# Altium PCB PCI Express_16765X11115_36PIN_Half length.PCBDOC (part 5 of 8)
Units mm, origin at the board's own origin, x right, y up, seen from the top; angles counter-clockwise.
Board outline 178 x 110.97 mm, 10 copper layers (Top Layer, Int1 (GND), Int2 (Sign), Int3 (Sign), Int4 (PWR), Int5 (GND), Int6 (Sign), Int7 (Sign), Int8 (GND), Bottom Layer), stack 1.429 mm thick; 528 components, 525 nets, 2272 pads, 1491 vias.
Unrouted connection lines stored in the file: 373.
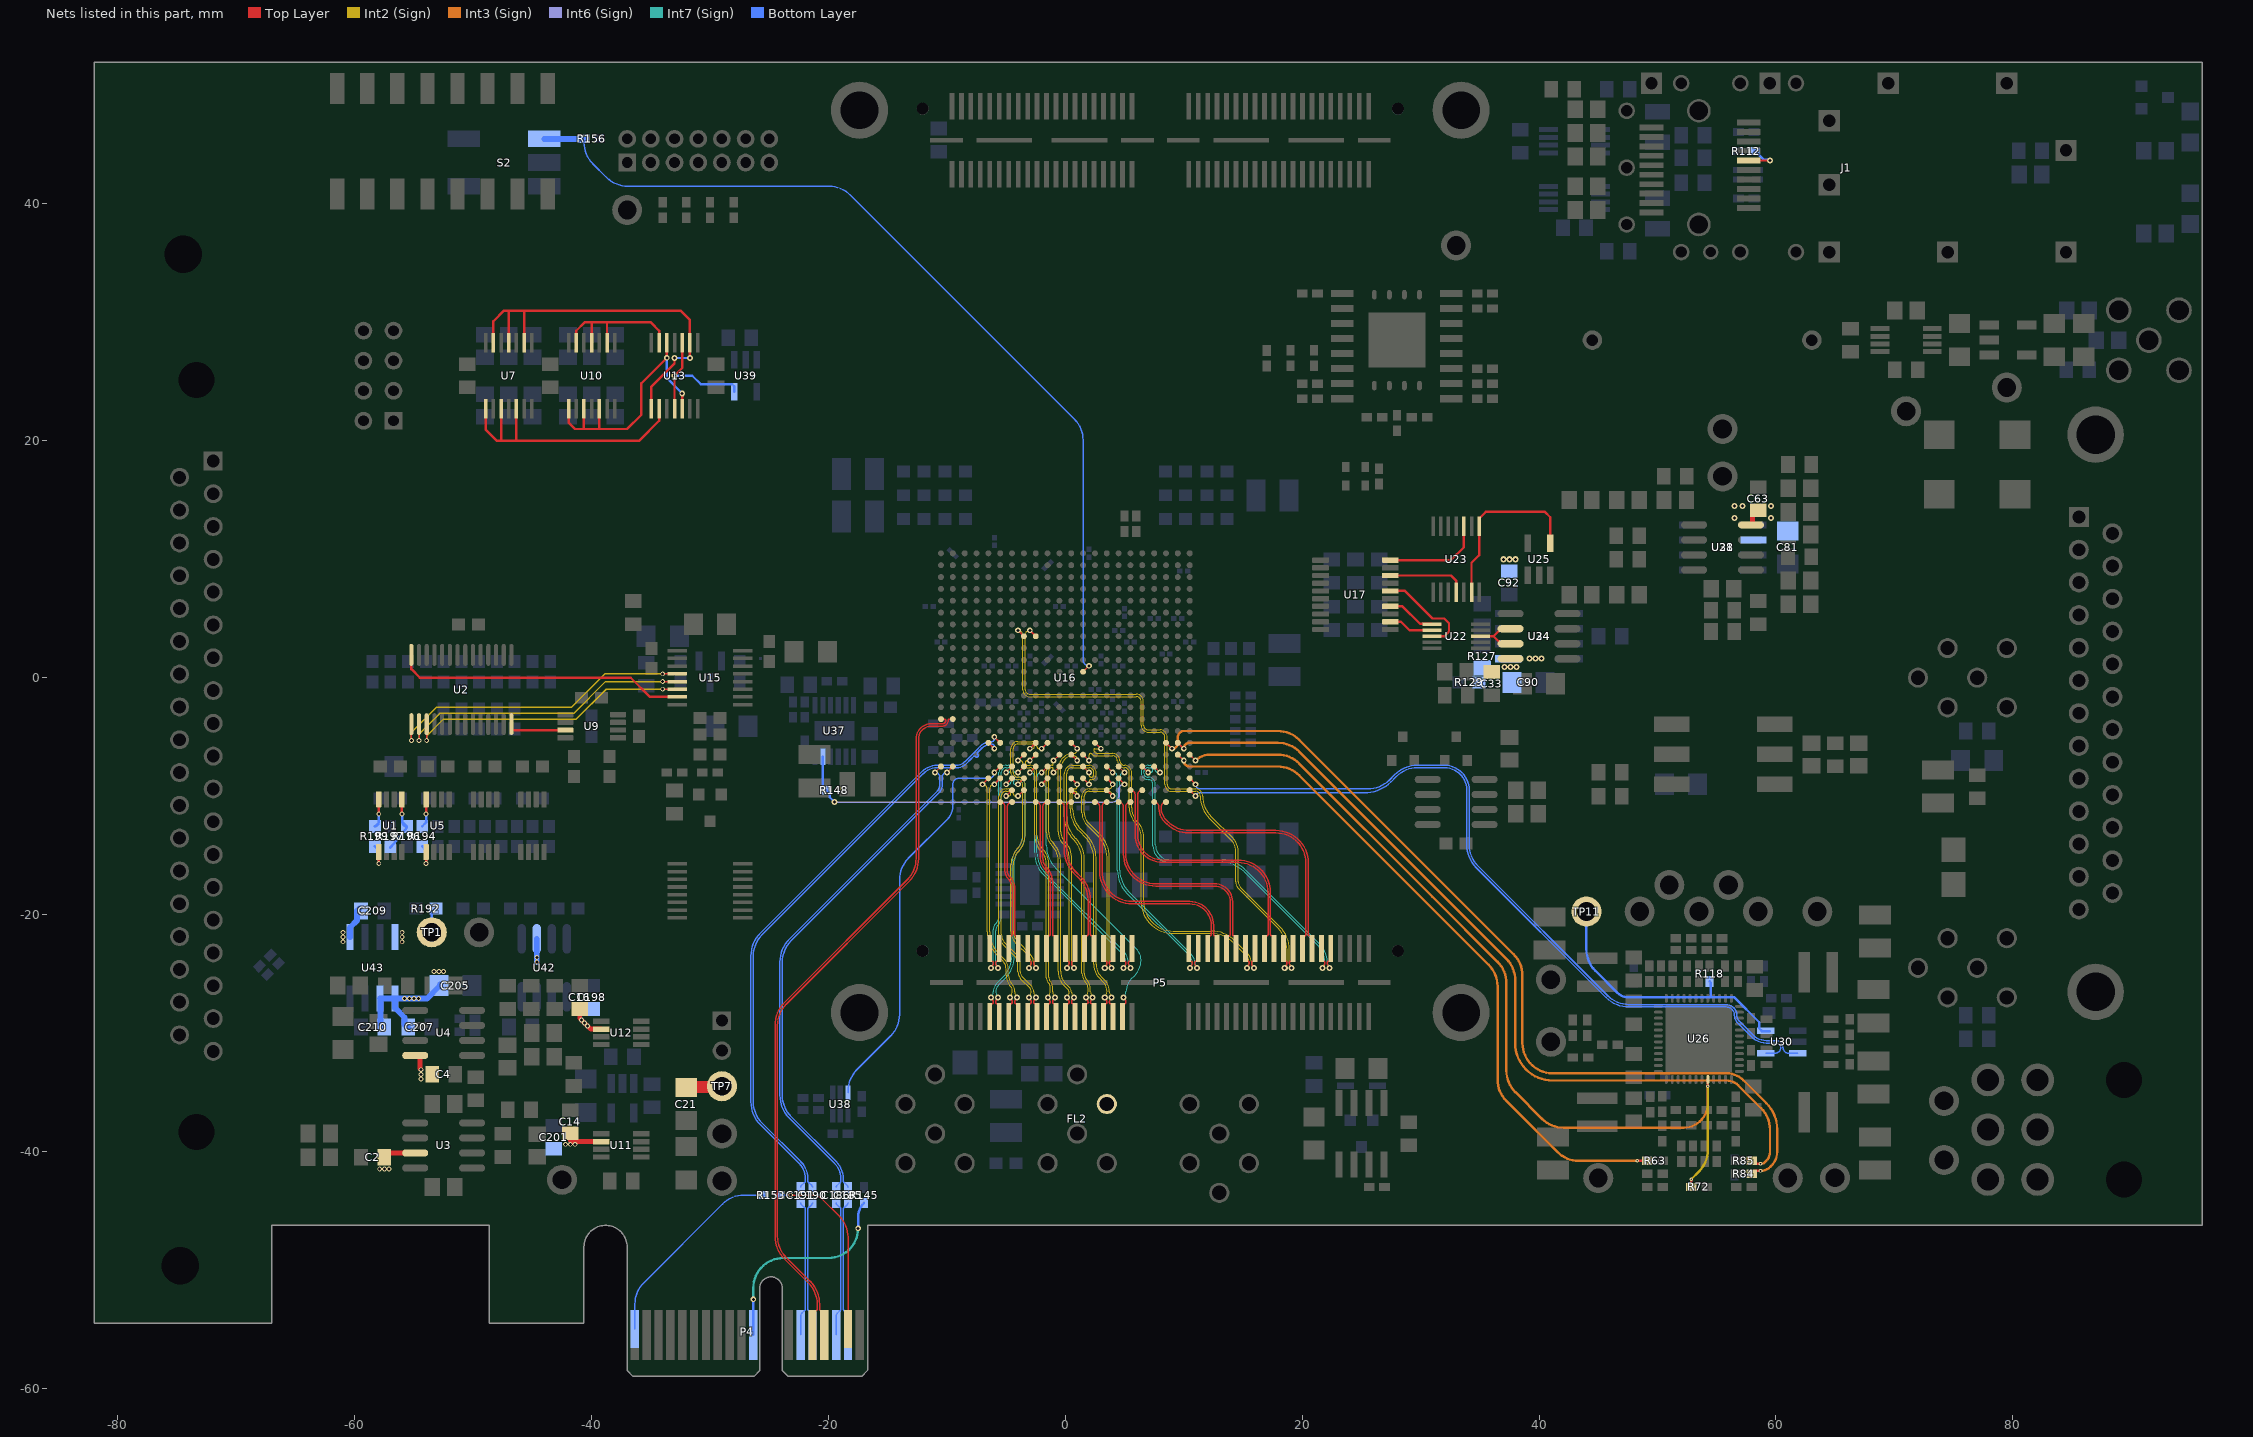
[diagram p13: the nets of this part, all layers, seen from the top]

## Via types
v1: diameter 0.483, hole 0.254, Top Layer to Bottom Layer, tented both sides, 740 vias
v2: diameter 0.508, hole 0.254, Top Layer to Bottom Layer, tented both sides, 302 vias
v3: diameter 0.406, hole 0.254, Top Layer to Bottom Layer, tented both sides, 267 vias
v4: diameter 0.305, hole 0.152, Top Layer to Bottom Layer, tented both sides, 95 vias
v5: diameter 0.5, hole 0.254, Top Layer to Bottom Layer, tented both sides, 50 vias
v6: diameter 0.45, hole 0.254, Top Layer to Bottom Layer, tented both sides, 23 vias
v7: diameter 0.6, hole 0.254, Top Layer to Bottom Layer, tented both sides, 14 vias

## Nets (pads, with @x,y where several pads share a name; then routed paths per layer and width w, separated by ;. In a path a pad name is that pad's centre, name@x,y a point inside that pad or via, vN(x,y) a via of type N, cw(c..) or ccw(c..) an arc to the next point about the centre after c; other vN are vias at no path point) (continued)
NetR194_1: R194.1 U5.8 | length 2.4
  Top Layer w0.203: v3(-53.975,-11.5) U5.8@-53.975,-10.275
  Bottom Layer w0.203: R194.1@-54.3,-12.55 R194.1@-53.975,-12.225 ; R194.1@-54,-12.2 R194.1@-53.975,-12.225 ; v3(-53.975,-11.5) R194.1@-53.975,-12.225
NetR194_2: R194.2 U5.1 | length 2.7
  Top Layer w0.203: v3@-53.975,-15.8 U5.1@-53.975,-14.725
  Bottom Layer w0.203: R194.2@-54.3,-14.25 -53.975,-14.575 v3(-53.975,-15.7)
NetR196_1: R196.1 R197.2 U1.5 | length 5.3
  Top Layer w0.203: v3(-56.025,-11.5) U1.5@-56.025,-10.275 cw(c-56.025,-10.3) U1.5@-56,-10.3
  Bottom Layer w0.203: R197.2@-57,-14.35 -56.951,-14.29 R196.1@-55.6,-12.65 ; v3(-56.025,-11.5) -55.998,-11.527 -55.998,-12.152 R196.1@-55.6,-12.55 cw(c-55.6,-12.15) R196.1@-56,-12.15
NetR199_1: R199.1 U1.8 | length 2.9
  Top Layer w0.203: U1.8@-58,-10.3 cw(c-57.975,-10.3) U1.8@-57.975,-10.275 v3(-57.975,-11.5)
  Bottom Layer w0.203: R199.1@-58,-12.25 cw(c-58.3,-12.25) R199.1@-58.3,-12.55 -57.975,-12.225 v3(-57.975,-11.5)
NetR199_2: R199.2 U1.1 | length 2.6
  Top Layer w0.203: v3(-57.975,-15.7) U1.1@-57.975,-14.725
  Bottom Layer w0.203: R199.2@-58.3,-14.25 -57.975,-14.575 -58,-14.6 -57.975,-14.625 v3(-57.975,-15.7)
NetU2_14: U2.14 U15.7 | length 24.6
  Top Layer w0.203: U2.14@-55.225,1.925 -55.225,0.725 -54.5,0 -36.7,0 -35.075,-1.625 U15.7@-32.775,-1.625
NetU2_15: U2.15 U15.4 | length 26.6
  Top Layer w0.127: v3(-55.225,-5.3) U2.15@-55.225,-3.925 ; v3(-34,0.325) U15.4@-32.775,0.325
  Int2 (Sign) w0.127: v3(-55.225,-5.3) -55.225,-4.625 -53.1,-2.5 -41.699,-2.5 -38.874,0.325 v3(-34,0.325)
NetU2_16: U2.16 U15.5 | length 25.5
  Top Layer w0.127: v3(-54.575,-5.3) U2.16@-54.575,-3.925 ; v3(-34,-0.325) U15.5@-32.775,-0.325
  Int2 (Sign) w0.127: v3(-54.575,-5.3) -54.575,-4.775 -52.8,-3 -41.499,-3 -38.824,-0.325 v3(-34,-0.325)
NetU2_17: U2.17 U15.6 | length 24.5
  Top Layer w0.127: v3(-53.925,-5.3) U2.17@-53.925,-3.925 ; v3(-34,-0.975) U15.6@-32.775,-0.975
  Int2 (Sign) w0.127: v3(-53.925,-5.3) -53.925,-4.925 -52.5,-3.5 -41.299,-3.5 -38.774,-0.975 v3(-34,-0.975)
NetU2_28: U2.28 U9.3 | length 4.9
  Top Layer w0.203: U2.28@-46.775,-3.925 -46.775,-4.357 -46.707,-4.425 -42.325,-4.425 U9.3@-42.3,-4.4
NetU7_1: U7.1 U7.3 U7.5 U13.9 | length 24
  Top Layer w0.203: U7.1@-48.95,22.725 -48.95,20.95 -48,20 -47.65,20 ; U7.3@-47.65,22.725 -47.65,20 ; U7.5@-46.35,22.725 -46.35,20.05 -46.4,20 ; U13.9@-34.3,22.725 -34.3,21.7 -36,20 -46.4,20 ; -47.65,20 -46.4,20
NetU7_9: U7.9 U7.11 U7.13 U13.2 U13.8 | length 34.2
  Top Layer w0.203: U7.13@-48.3,28.275 -48.3,30.1 -47.4,31 -47,31 ; U7.11@-47,28.275 -47,31 ; U7.9@-45.7,28.275 -45.7,31 ; U13.8@-34.95,22.725 -34.95,24.592 -33,26.542 v1(-33,26.995) ; v1(-31.7,26.995) U13.2@-31.7,28.275 -31.7,30.2 -32.5,31 -45.7,31 ; -47,31 -45.7,31
  Bottom Layer w0.203: v1(-33,26.995) v1(-31.7,26.995)
NetU10_1: U10.1 U10.3 U10.5 U13.5 U13.12 | length 23.3
  Top Layer w0.203: U10.1@-41.95,22.725 -41.95,21.55 -41.4,21 -40.653,21 -39.3,21 ; -40.653,21.006 -40.65,21.008 U10.3@-40.65,22.725 ; U10.5@-39.35,22.725 -39.35,21.05 -39.3,21 ; U13.5@-33.65,28.275 v1(-33.65,27.013) -35.8,24.862 -35.8,22.2 -37,21 -39.3,21 ; U13.12@-32.35,22.725 v1(-32.35,24)
  Bottom Layer w0.203: v1(-33.65,27.013) -33.65,25.3 v1(-32.35,24)
NetU10_9: U10.9 U10.11 U10.13 U13.6 | length 13.1
  Top Layer w0.203: U10.13@-41.3,28.275 -41.3,29.3 -40.6,30 -40,30 ; U10.11@-40,28.275 -40,30 ; U10.9@-38.7,28.275 -38.7,30 ; U13.6@-34.3,28.275 -34.3,29.3 -35,30 -38.7,30 ; -40,30 -38.7,30
NetU13_3: U13.3 U13.11 U39.5 | length 11.5
  Top Layer w0.203: U13.11@-33,22.9 v1(-33,25.5) -32.35,26.15 U13.3@-32.35,28.275
  Bottom Layer w0.203: v1(-33,25.5) -31.5,25.5 -30.773,24.773 -28.123,24.773 -27.95,24.6 U39.5@-27.95,24.15
NetU17_12: U17.12 U22.7 | length 3.8
  Top Layer w0.203: U17.12@27.45,4.725 28.343,4.725 29.068,4 U22.7@30.95,4
NetU17_14: U17.14 U22.6 | length 4.1
  Top Layer w0.203: U17.14@27.45,6.025 28.475,6.025 29.952,4.548 30.902,4.548 U22.6@30.95,4.5
NetU17_16: U17.16 U22.8 | length 8.4
  Top Layer w0.203: U17.16@27.45,7.325 28.675,7.325 31,5 32,5 32.4,4.6 32.4,3.9 32,3.5 U22.8@30.95,3.5
NetU17_18: U17.18 U23.11 | length 6.6
  Top Layer w0.203: U17.18@27.6,8.6 27.625,8.625 32.575,8.625 33,8.2 U23.11@33,7.225
NetU17_20: U17.20 U23.3 | length 8.4
  Top Layer w0.203: U17.20@27.45,9.925 32.56,9.925 33.65,11.015 U23.3@33.65,12.775
NetU22_3: U22.3 U24.6 U24.7 | length 5
  Top Layer w0.203: U22.3@35.05,3.5 36.165,3.5 ; U24.7@37.8,2.8 36.865,2.8 36.165,3.5 ; U24.6@37.8,4.2 36.865,4.2 36.165,3.5
NetU23_1: U23.1 U23.13 U25.4 | length 15.1
  Top Layer w0.203: U23.13@34.3,7.2 34.3,9.7 34.95,10.35 34.95,13.45 34.998,13.498 35.5,14 40.5,14 40.95,13.55 U25.4@40.95,11.35
P5V: C2.2 C4.2 C14.1 C16.1 C198.1 C201.1 C205.2 C207.2 C210.2 R192.1 TP1.1 U3.7 U4.8 U11.2 U12.2 U42.2 U43.1 U43.2 | length 25.1
  Top Layer w0.406: C2.2@-57.5,-40.5 -57.135,-40.135 U3.7@-54.935,-40.135 ; U3.7@-54.9,-40.135 U3.7@-54.935,-40.135 ; U3.7@-54.9,-40.1 U3.7@-54.935,-40.135 ; U4.8@-54.9,-31.905 -54.587,-31.905 -54.497,-31.995 -54.497,-33.003 v3(-54.4,-33.1) ; -41.8,-39.1 -41.725,-39.175 U11.2@-39.2,-39.175 ; C16.1@-41,-27.975 -41,-28.749 -40.074,-29.675 U12.2@-39.2,-29.675
  Bottom Layer w0.203: TP1.1@-53.5,-21.5 -53.5,-19.85 R192.1@-53.15,-19.5
  Bottom Layer w0.5: U43.2@-57.865,-27.1 -57.815,-27.15 -57.815,-29.185 C210.2@-57.6,-29.4 ; U43.2@-57.8,-27.1 U43.1@-56.595,-27.1 ; C207.2@-55.4,-29.7 -55.8,-29.3 -55.8,-28.695 -56.595,-27.9 U43.1@-56.595,-27.1 ; C205.2@-52.8,-25.9 -52.8,-26 -53.9,-27.1 U43.1@-56.595,-27.1 ; v3(-44.635,-24) U42.2@-44.635,-22.05
  other v3: -57.9,-41.5 -57.5,-41.5 -57.1,-41.5 -42.2,-39.4 -41.8,-39.4 -41.4,-39.4 -54.4,-33.9 -54.4,-33.5 -40.349,-29.4 -40.612,-29.16 -40.849,-28.9 -55.8,-27.1 -55.4,-27.1 -55,-27.1 -54.6,-27.1 -53.3,-24.8 -52.9,-24.8 -52.5,-24.8 -44.635,-23.611
P10V: C33.2 C63.2 C81.1 C90.1 C92.1 R127.2 R129.1 U24.8 U28.8 U31.2 U34.1 | length 1.6
  Top Layer w0.455: U28.8@57.9,12.905 57.961,12.905 58.027,12.972 58.027,13.777 58.375,14.125 C63.2@58.5,14.125
  other v2: 37.1,0.9 37.6,0.9 38.1,0.9 39.2,1.6 39.7,1.6 40.2,1.6 37,10 37.5,10 38,10 56.5,13.5 59.6,13.5 56.5,14.5 57.2,14.5 59.6,14.5
P12V: C21.2 C209.2 FL2.2 TP7.1 U43.5 U43.8 | length 5.8
  Top Layer w1: C21.2@-32,-34.6 -31.95,-34.55 -29.05,-34.55 TP7.1@-29,-34.5
  Bottom Layer w0.5: U43.5@-60.405,-21.9 -60.405,-21.1 -59.8,-20.495 -59.8,-19.7 C209.2@-59.6,-19.5
  other v3: -61,-22.3 -56,-22.3 -61,-21.9 -56,-21.9 -61,-21.5 -56,-21.5
P_SYNC: R118.2 TP11.1 U30.5 | length 23.7
  Bottom Layer w0.203: TP11.1@44,-19.75 44,-22.941 ccw(c46.54,-22.941) 44.744,-24.737 46.621,-26.614 ccw(c47.552,-25.683) 47.552,-27 54.5,-27 ; R118.2@54.4,-25.65 54.5,-25.75 54.5,-27 ; U30.5@59.49,-29.85 58.823,-29.85 58.6,-29.627 58.6,-29.1 56.5,-27 54.5,-27
PCIE.PCIE_CLK_N: C190.2 U16.E6 | length 50.8
  Top Layer w0.127: U16.E6@-6.5,-5.5 v1(-6,-6)
  Bottom Layer w0.127: C190.2@-21.344,-43.037 ccw(c-21.585,-43.037) -21.414,-42.867 -21.616,-42.665 ccw(c-21.651,-42.7) -21.651,-42.651 cw(c-21.651,-42.602) -21.685,-42.637 cw(c-21.54,-42.492) -21.745,-42.492 -21.745,-42.297 ccw(c-23.749,-42.297) -22.332,-40.88 -25.606,-37.607 cw(c-23.81,-35.811) -26.35,-35.811 -26.35,-23.502 cw(c-23.81,-23.502) -25.606,-21.706 -12.004,-8.103 cw(c-10.796,-9.311) -10.796,-7.603 -9.738,-7.603 -9.198,-7.603 ccw(c-9.198,-6.409) -8.353,-7.253 -8.335,-7.235 -7.98,-6.88 -7.757,-6.657 cw(c-7.667,-6.747) -7.577,-6.657 -7.567,-6.668 ccw(c-7.477,-6.579) -7.388,-6.668 ccw(c-7.477,-6.579) -7.388,-6.49 -7.399,-6.479 cw(c-7.309,-6.389) -7.399,-6.299 -7.056,-5.956 cw(c-6.2,-6.813) -6.2,-5.602 cw(c-6.2,-5.802) -6,-5.802 v1(-6,-6)
PCIE.PCIE_CLK_P: C191.2 U16.F6 | length 50.8
  Top Layer w0.127: v1(-6,-5) U16.F6@-5.5,-5.5
  Bottom Layer w0.127: C191.2@-22.35,-43.037 cw(c-22.109,-43.037) -22.279,-42.867 -22.078,-42.665 cw(c-22.043,-42.7) -22.043,-42.651 ccw(c-22.043,-42.602) -22.009,-42.637 ccw(c-22.153,-42.492) -21.948,-42.492 -21.948,-42.3 ccw(c-23.755,-42.3) -22.478,-41.022 -25.75,-37.75 cw(c-23.811,-35.811) -26.553,-35.811 -26.553,-23.501 cw(c-23.813,-23.501) -25.75,-21.563 -12.144,-7.957 cw(c-10.8,-9.302) -10.8,-7.4 -9.2,-7.4 ccw(c-9.2,-6.404) -8.496,-7.108 -8.479,-7.091 -7.444,-6.056 -7.199,-5.812 cw(c-6.201,-6.811) -6.202,-5.398 ; -6.2,-5.398 ccw(c-6.2,-5.198) -6,-5.198 v1(-6,-5)
PCIE.PCIE_PERST: U16.F4 U38.3 | length 34.1
  Top Layer w0.127: v1(-6,-8) U16.F4@-5.5,-7.5
  Bottom Layer w0.127: U38.3@-18.35,-35.05 -18.35,-34.902 cw(c-15.81,-34.902) -17.606,-33.106 -14.744,-30.244 ccw(c-16.54,-28.448) -14,-28.448 -14,-17.052 cw(c-11.46,-17.052) -13.256,-15.256 -10,-12 ccw(c-11.207,-10.793) -9.5,-10.793 -9.5,-8.998 cw(c-9.002,-8.998) -9.002,-8.5 -6.5,-8.5 ccw(c-6.5,-8) v1(-6,-8)
PCIE.PCIE_PWRGD: R148.1 U16.T3 U37.5 | length 30.5
  Top Layer w0.127: U16.T3@4.5,-8.5 v1(5,-9)
  Int6 (Sign) w0.127: v1(-19.5,-10.5) 4,-10.5 ccw(c4,-10) 4.5,-10 4.5,-9.5 cw(c5,-9.5) v1(5,-9)
  Bottom Layer w0.203: U37.5@-20.475,-6.684 -20.475,-9.252 R148.1@-20.227,-9.5 ; R148.1@-20.15,-9.5 -20.148,-9.5 -19.9,-9.748 -19.9,-10.1 v1(-19.5,-10.5)
PCIE.PCIE_RX0_N: P4.B14 U16.A8 | length 60.3
  Top Layer w0.127: P4.B14@-21.35,-55.5 -21.35,-53.953 cw(c-20.861,-53.953) -21.207,-53.607 -21.077,-53.477 cw(c-21.045,-53.509) -21.045,-53.463 ccw(c-21.045,-53.418) -21.013,-53.45 ccw(c-21.16,-53.303) -20.952,-53.303 -20.952,-52.909 ccw(c-23.492,-52.909) -21.696,-51.113 -23.713,-49.096 cw(c-21.774,-47.157) -24.516,-47.157 -24.516,-29.364 cw(c-21.775,-29.364) -23.713,-27.426 -13.344,-17.057 ccw(c-15.14,-15.261) -12.6,-15.261 -12.6,-5.169 cw(c-11.327,-5.169) -11.327,-3.896 -10.381,-3.896 ccw(c-10.381,-3.617) -10.102,-3.617 ccw(c-10.218,-3.617) -10.218,-3.5 U16.A8@-10.5,-3.5
PCIE.PCIE_RX0_P: P4.B15 U16.B8 | length 60.3
  Top Layer w0.127: P4.B15@-20.655,-53.463 cw(c-20.655,-53.418) -20.687,-53.45 cw(c-20.54,-53.303) -20.748,-53.303 -20.748,-52.906 ccw(c-23.486,-52.906) -21.55,-50.971 -23.569,-48.952 cw(c-21.772,-47.156) -24.312,-47.156 -24.312,-29.365 cw(c-21.772,-29.365) -23.569,-27.569 -13.2,-17.2 ccw(c-15.137,-15.262) -12.397,-15.262 -12.397,-5.17 cw(c-11.326,-5.17) -11.326,-4.099 -10.381,-4.099 ccw(c-10.381,-3.617) -9.898,-3.617 cw(c-9.782,-3.617) -9.782,-3.5 U16.B8@-9.5,-3.5 ; P4.B15@-20.623,-53.477 -20.493,-53.607 cw(c-20.839,-53.953) -20.35,-53.953 P4.B15@-20.35,-55.5
PCIE.PCIE_TX0_N: C186.2 U16.A4 | length 43.5
  Top Layer w0.127: v1(-11,-8) U16.A4@-10.5,-7.5
  Bottom Layer w0.127: C186.2@-19.35,-43.044 cw(c-19.109,-43.044) -19.279,-42.873 -19.077,-42.67 cw(c-19.045,-42.703) -19.045,-42.657 ccw(c-19.045,-42.612) -19.013,-42.644 ccw(c-19.16,-42.496) -18.952,-42.496 -18.952,-42.324 ccw(c-20.824,-42.324) -19.5,-41 -23.3,-37.2 cw(c-21.363,-35.262) -24.103,-35.262 -24.103,-24.016 cw(c-21.363,-24.016) -24.103,-24.013 cw(c-21.363,-24.016) -23.3,-22.079 -10.87,-9.648 ccw(c-11.518,-9) -10.602,-9 -10.602,-8.398 ccw(c-11,-8.398) v1(-11,-8)
PCIE.PCIE_TX0_P: C185.2 U16.B4 | length 43.5
  Top Layer w0.127: v1(-10,-8) U16.B4@-9.5,-7.5
  Bottom Layer w0.127: C185.2@-18.655,-42.657 cw(c-18.655,-42.612) -18.687,-42.644 cw(c-18.54,-42.496) -18.748,-42.496 -18.748,-42.32 ccw(c-20.814,-42.32) -19.353,-40.859 -23.156,-37.057 cw(c-21.36,-35.261) -23.9,-35.261 -23.9,-24.018 cw(c-21.36,-24.018) -23.156,-22.221 -10.726,-9.792 ccw(c-11.518,-9) -10.398,-9 -10.398,-8.398 cw(c-10,-8.398) v1(-10,-8) ; C185.2@-18.623,-42.67 -18.421,-42.873 cw(c-18.591,-43.044) C185.2@-18.35,-43.044
PER0_N: C185.1 P4.A17 | length 11.5
  Bottom Layer w0.127: P4.A17@-18.35,-55.5 -18.35,-53.953 ccw(c-18.839,-53.953) -18.493,-53.607 -18.623,-53.477 ccw(c-18.655,-53.509) -18.655,-53.463 cw(c-18.655,-53.418) -18.687,-53.45 cw(c-18.54,-53.303) -18.748,-53.303 -18.748,-44.891 cw(c-18.54,-44.891) -18.687,-44.744 cw(c-18.655,-44.776) -18.655,-44.73 ccw(c-18.655,-44.685) -18.623,-44.717 -18.421,-44.514 ccw(c-18.591,-44.344) C185.1@-18.35,-44.344
PER0_P: C186.1 P4.A16 | length 11.5
  Bottom Layer w0.127: P4.A16@-19.35,-55.5 -19.35,-53.953 cw(c-18.861,-53.953) -19.207,-53.607 -19.077,-53.477 cw(c-19.045,-53.509) -19.045,-53.463 ccw(c-19.045,-53.418) -19.013,-53.45 ccw(c-19.16,-53.303) -18.952,-53.303 -18.952,-44.891 ccw(c-19.16,-44.891) -19.013,-44.744 ccw(c-19.045,-44.776) -19.045,-44.73 cw(c-19.045,-44.685) -19.077,-44.717 -19.279,-44.514 cw(c-19.109,-44.344) C186.1@-19.35,-44.344
PERST#: P4.A11 R145.1 | length 18
  Int7 (Sign) w0.203: v6(-26.35,-52.5) -26.35,-51.54 cw(c-23.81,-51.54) -23.81,-49 -19.99,-49 ccw(c-19.99,-46.51) -17.5,-46.51 v6(-17.5,-46.5)
  Bottom Layer w0.203: P4.A11@-26.35,-55.5 v6(-26.35,-52.5) ; v6(-17.5,-46.5) -17.5,-45.557 cw(c-15.793,-45.557) R145.1@-17.001,-44.351
POWER.PWRGOOD: R72.1 U16.AB5 U26.20 | length 74.4
  Top Layer w0.127: U16.AB5@10.5,-6.5 v1(11,-7)
  Top Layer w0.203: R72.1@52.85,-43 v4(52.85,-42.35) ; v4(54.25,-34.5) U26.20@54.25,-33.925
  Int3 (Sign) w0.203: v1(11,-7) cw(c12.207,-8.207) 12.207,-6.5 17.948,-6.5 cw(c17.948,-9.04) 19.744,-7.244 31,-18.5 36.5,-24 cw(c34.704,-25.796) 37.244,-25.796 37.244,-33.192 ccw(c39.784,-33.192) 37.988,-34.988 ; 38,-35 40.256,-37.256 ccw(c42.052,-35.46) 42.052,-38 52.21,-38 ccw(c52.21,-35.96) 54.25,-35.96 v4(54.25,-34.5)
  Int2 (Sign) w0.203: v4(52.85,-42.35) 53.506,-41.694 ccw(c51.71,-39.898) 54.25,-39.898 v4(54.25,-34.5)
POWER.PWRINT: R63.1 U16.AA5 | length 59.4
  Top Layer w0.127: U16.AA5@9.5,-6.5 v1(10,-7)
  Top Layer w0.203: v4(48.3,-40.8) R63.1@49.15,-40.8
  Int3 (Sign) w0.203: v1(10,-7) ccw(c10.5,-7) 10.5,-7.5 17.948,-7.5 cw(c17.948,-10.04) 19.744,-8.244 30.5,-19 35.756,-24.256 cw(c33.96,-26.052) 36.5,-26.052 36.5,-33.948 ccw(c39.04,-33.948) 37.244,-35.744 41.556,-40.056 ccw(c43.352,-38.26) 43.352,-40.8 v4(48.3,-40.8)
POWER.PWRSCL: R85.1 U16.AA6 | length 72.7
  Top Layer w0.127: U16.AA6@9.5,-5.5 v1(10,-6) ; R85.1@57.95,-40.8 R85.1@58.017,-40.733
  Top Layer w0.203: R85.1@57.95,-40.8 58.198,-41.049 58.699,-41.049 v4(58.7,-41.05)
  Int3 (Sign) w0.203: v1(10,-6) cw(c10.5,-6) 10.5,-5.5 17.948,-5.5 cw(c17.948,-8.04) 19.744,-6.244 37.244,-23.744 cw(c35.448,-25.54) 37.988,-25.54 37.988,-30.86 ccw(c41.14,-30.86) 41.14,-34.012 55.824,-34.012 cw(c55.824,-35.431) 56.828,-34.428 58.756,-36.356 cw(c56.96,-38.152) 59.5,-38.152 59.5,-40.049 cw(c58.438,-40.049) 59.189,-40.8 59.108,-40.881 cw(c58.7,-40.473) v4(58.7,-41.05)
POWER.PWRSDA: R84.1 U16.Y6 | length 76.6
  Top Layer w0.127: U16.Y6@8.5,-5.5 v1(9,-6)
  Top Layer w0.203: R84.1@57.95,-41.9 58.198,-41.652 58.698,-41.652 v4(58.7,-41.65)
  Int3 (Sign) w0.203: v1(9,-6) ccw(c9,-5.5) 9.5,-5.5 9.5,-5 cw(c10,-5) 10,-4.5 17.948,-4.5 cw(c17.948,-7.04) 19.744,-5.244 37.856,-23.356 cw(c36.06,-25.152) 38.6,-25.152 38.6,-30.86 ccw(c41.14,-30.86) 41.14,-33.4 55.824,-33.4 cw(c55.824,-35.431) 57.261,-33.995 59.189,-35.923 cw(c56.96,-38.152) 60.112,-38.152 60.112,-40.02 cw(c58.409,-40.02) 59.613,-41.224 59.532,-41.305 cw(c58.7,-40.473) v4(58.7,-41.65)
POWER.PWRSYNC_N: U16.AB2 U30.4 | length 65.9
  Top Layer w0.127: U16.AB2@10.5,-9.5 v1(11,-10)
  Bottom Layer w0.127: v1(11,-10) cw(c11.267,-10) 11.267,-9.733 25.233,-9.733 ccw(c25.233,-6.543) 27.488,-8.799 27.943,-8.344 cw(c29.739,-10.14) 29.739,-7.6 32,-7.6 cw(c32,-9.5) 33.9,-9.5 33.9,-14.108 ccw(c36.642,-14.108) 34.703,-16.046 45.657,-27 ccw(c47.595,-25.061) 47.595,-27.803 55.803,-27.803 cw(c55.803,-28.5) 56.5,-28.5 ; 56.5,-28.501 ccw(c57.434,-28.501) 56.773,-29.161 57.958,-30.346 ccw(c59.176,-29.128) 59.173,-30.85 ccw(c59.176,-29.128) 59.176,-30.85 59.998,-30.85 cw(c59.998,-31.25) 60.398,-31.25 cw(c59.948,-31.25) 59.948,-31.7 U30.4@59.15,-31.7
POWER.PWRSYNC_P: U16.AB3 U30.3 | length 66.3
  Top Layer w0.127: U16.AB3@10.5,-8.5 v1(11,-9)
  Bottom Layer w0.127: v1(11,-9) ccw(c11.398,-9) 11.398,-9.398 25.549,-9.398 ccw(c25.549,-6.858) 27.346,-8.654 27.8,-8.2 cw(c29.738,-10.137) 29.738,-7.397 32,-7.397 cw(c32,-9.5) 34.103,-9.5 34.103,-14.107 ccw(c36.643,-14.107) 34.847,-15.903 45.8,-26.856 ccw(c47.596,-25.06) 47.596,-27.6 55.803,-27.6 cw(c55.803,-28.5) 56.703,-28.5 ccw(c57.435,-28.5) 56.918,-29.018 58.1,-30.2 ccw(c59.179,-29.121) 59.176,-30.647 ccw(c59.179,-29.121) 59.179,-30.647 59.998,-30.647 cw(c59.998,-31.25) 60.602,-31.25 ccw(c61.052,-31.25) 61.052,-31.7 U30.3@61.85,-31.7
PROG: R156.1 S2.1 U16.N12 | length 77.1
  Top Layer w0.127: U16.N12@1.5,0.5 v1(2,1)
  Bottom Layer w0.127: R156.1@-40.65,45.5 -40.65,45.202 ccw(c-38.11,45.202) -39.906,43.406 -38.744,42.244 ccw(c-36.948,44.04) -36.948,41.5 -19.952,41.5 cw(c-19.952,38.96) -18.156,40.756 0.756,21.844 cw(c-1.04,20.048) 1.5,20.048 1.5,1.5 ccw(c2,1.5) v1(2,1)
  Bottom Layer w0.5: S2.1@-44,45.5 R156.1@-40.65,45.5
PRSNT1#: P4.A1 R153.2 | length 17.3
  Bottom Layer w0.127: P4.A1@-36.35,-55 -36.35,-52.902 cw(c-33.81,-52.902) -35.606,-51.106 -28.944,-44.444 cw(c-27.148,-46.24) -27.148,-43.7 R153.2@-25.4,-43.7
PRSNT2#: P4.B17 R153.1 | length 15.5
  Top Layer w0.127: v6(-23.227,-43.687) -21.405,-43.687 cw(c-21.405,-44.968) -20.5,-44.062 -19.094,-45.469 cw(c-20.89,-47.265) -18.35,-47.265 P4.B17@-18.35,-55
  Bottom Layer w0.127: R153.1@-24.163,-43.687 v6(-23.227,-43.687)
RDY: J1.6 R112.1 | length 3.5
  Top Layer w0.203: J1.6@57.7,43.67 v1(59.5,43.67)
  Bottom Layer w0.203: R112.1@58.15,44.47 58.25,44.47 58.997,43.723 59.447,43.723 v1(59.5,43.67)
REFCLK_N: C190.1 P4.A14 | length 11.5
  Bottom Layer w0.127: P4.A14@-21.35,-55.5 -21.35,-53.953 ccw(c-21.839,-53.953) -21.493,-53.607 -21.623,-53.477 ccw(c-21.655,-53.509) -21.655,-53.463 cw(c-21.655,-53.418) -21.687,-53.45 cw(c-21.54,-53.303) -21.748,-53.303 -21.748,-45.021 -21.745,-45.018 -21.745,-44.851 cw(c-21.618,-44.851) -21.708,-44.761 -21.685,-44.738 cw(c-21.651,-44.773) -21.651,-44.724 ccw(c-21.651,-44.675) -21.616,-44.71 -21.414,-44.508 ccw(c-21.585,-44.337) C190.1@-21.344,-44.337
REFCLK_P: C191.1 P4.A13 | length 11.5
  Bottom Layer w0.127: P4.A13@-22.35,-55.5 -22.35,-53.953 cw(c-21.861,-53.953) -22.207,-53.607 -22.077,-53.477 cw(c-22.045,-53.509) -22.045,-53.463 ccw(c-22.045,-53.418) -22.013,-53.45 ccw(c-22.16,-53.303) -21.952,-53.303 -21.952,-44.937 -21.948,-44.934 -21.948,-44.851 ccw(c-22.075,-44.851) -21.986,-44.761 -22.009,-44.738 ccw(c-22.043,-44.773) -22.043,-44.724 cw(c-22.043,-44.675) -22.078,-44.71 -22.279,-44.508 cw(c-22.109,-44.337) C191.1@-22.35,-44.337
S1_16.S1_N: P5.12 U16.G4 | length 20.9
  Top Layer w0.127: v2(-5.688,-24.5) ccw(c-5.867,-24.5) -5.74,-24.373 -5.853,-24.26 cw(c-5.793,-24.2) -5.878,-24.2 -5.878,-24.08 cw(c-5.726,-24.08) -5.833,-23.972 cw(c-5.761,-24.044) -5.761,-23.942 ccw(c-5.761,-23.84) -5.689,-23.912 -5.649,-23.872 ccw(c-5.818,-23.704) -5.58,-23.704 P5.12@-5.58,-22.875 ; v1(-5,-8) U16.G4@-4.5,-7.5
  Int7 (Sign) w0.076: v2(-5.688,-24.5) ccw(c-5.857,-24.5) -5.737,-24.38 cw(c-5.397,-24.04) -5.878,-24.04 -5.878,-21.379 cw(c-5.062,-21.379) -5.639,-20.802 ccw(c-6.216,-20.225) -5.4,-20.225 -5.4,-8 cw(c-5,-8) -5,-7.6 -4.802,-7.6 cw(c-4.802,-7.8) -4.602,-7.8 cw(c-4.802,-7.8) -4.802,-8 v1(-5,-8)
S1_16.S1_P: P5.10 U16.H4 | length 21.5
  Top Layer w0.127: P5.10@-6.38,-22.875 -6.38,-23.704 ccw(c-6.141,-23.704) -6.31,-23.872 -6.27,-23.912 ccw(c-6.198,-23.84) -6.198,-23.942 cw(c-6.198,-24.044) -6.126,-23.972 cw(c-6.233,-24.08) -6.081,-24.08 -6.081,-24.2 cw(c-6.166,-24.2) -6.106,-24.26 -6.219,-24.373 ccw(c-6.092,-24.5) v2(-6.272,-24.5) ; v1(-4,-8) U16.H4@-3.5,-7.5
  Int7 (Sign) w0.076: v2(-6.272,-24.5) cw(c-6.103,-24.5) -6.222,-24.38 ccw(c-6.563,-24.04) -6.081,-24.04 -6.081,-21.294 cw(c-5.265,-21.294) -5.842,-20.717 ccw(c-6.419,-20.14) -5.603,-20.14 -5.603,-8 cw(c-5,-8) -5,-7.397 -4.802,-7.397 cw(c-4.802,-7.8) -4.398,-7.8 ccw(c-4.198,-7.8) -4.198,-8 v1(-4,-8)
S1_16.S2_N: P5.14 U16.F1 | length 12.9
  Top Layer w0.127: U16.F1@-5.5,-10.5 cw(c-5.5,-10.898) -5.102,-10.898 -5.102,-16.322 ccw(c-4.225,-16.322) -4.845,-16.943 -4.844,-16.944 cw(c-5.718,-17.818) -4.481,-17.818 -4.481,-21.681 cw(c-4.608,-21.681) -4.519,-21.771 -4.526,-21.779 cw(c-4.598,-21.707) -4.598,-21.809 ccw(c-4.598,-21.91) -4.67,-21.838 ccw(c-4.405,-22.104) -4.78,-22.104 P5.14@-4.78,-22.875
S1_16.S2_P: P5.16 U16.G1 | length 12.9
  Top Layer w0.127: U16.G1@-4.5,-10.5 ccw(c-4.5,-10.898) -4.898,-10.898 -4.898,-16.321 ccw(c-4.221,-16.321) -4.7,-16.8 -4.698,-16.802 cw(c-5.71,-17.815) -4.278,-17.815 -4.278,-21.681 ccw(c-4.151,-21.681) -4.241,-21.771 -4.234,-21.779 ccw(c-4.162,-21.707) -4.162,-21.809 cw(c-4.162,-21.91) -4.09,-21.838 cw(c-4.355,-22.104) -3.98,-22.104 P5.16@-3.98,-22.875
S1_16.S3_N: P5.20 U16.J6 | length 25.2
  Top Layer w0.127: v1(-3,-6) U16.J6@-2.5,-5.5 ; v2(-2.488,-24.5) ccw(c-2.667,-24.5) -2.54,-24.373 -2.583,-24.33 cw(c-2.353,-24.1) -2.678,-24.1 -2.678,-24.08 cw(c-2.526,-24.08) -2.633,-23.972 cw(c-2.561,-24.044) -2.561,-23.942 ccw(c-2.561,-23.84) -2.489,-23.912 -2.449,-23.872 ccw(c-2.618,-23.704) -2.38,-23.704 P5.20@-2.38,-22.875
  Int2 (Sign) w0.076: v1(-3,-6) -2.802,-6 ccw(c-2.802,-5.8) -2.602,-5.8 ccw(c-2.802,-5.8) -2.802,-5.6 -4,-5.6 ccw(c-4,-6) -4.4,-6 -4.4,-8 ccw(c-4,-8) -4,-8.4 -3.997,-8.4 cw(c-3.997,-9) -3.397,-9 -3.397,-13.39 cw(c-5.103,-13.39) -3.897,-14.597 -3.9,-14.6 ccw(c-2.701,-15.799) -4.397,-15.799 -4.397,-21.297 -4.4,-21.3 -4.4,-21.4 ccw(c-3.162,-21.4) -4.038,-22.275 -2.964,-23.348 cw(c-3.655,-24.039) -2.678,-24.039 ccw(c-2.197,-24.04) -2.537,-24.38 cw(c-2.657,-24.5) v2(-2.488,-24.5)
S1_16.S3_P: P5.18 U16.K6 | length 25.8
  Top Layer w0.127: P5.18@-3.18,-22.875 -3.18,-23.704 ccw(c-2.941,-23.704) -3.11,-23.872 -3.07,-23.912 ccw(c-2.998,-23.84) -2.998,-23.942 cw(c-2.998,-24.044) -2.926,-23.972 cw(c-3.033,-24.08) -2.881,-24.08 -2.881,-24.1 cw(c-3.206,-24.1) -2.976,-24.33 -3.019,-24.373 ccw(c-2.892,-24.5) v2(-3.072,-24.5) ; v1(-2,-6) U16.K6@-1.5,-5.5
  Int2 (Sign) w0.076: v2(-3.072,-24.5) cw(c-2.903,-24.5) -3.022,-24.38 ccw(c-3.363,-24.04) -2.881,-24.04 ccw(c-3.657,-24.04) -3.108,-23.492 -4.182,-22.418 cw(c-3.164,-21.401) -4.603,-21.401 -4.603,-21.2 -4.6,-21.197 -4.6,-15.795 cw(c-2.711,-15.795) -4.047,-14.459 -4.044,-14.456 ccw(c-5.115,-13.385) -3.6,-13.385 -3.6,-9 ccw(c-3.997,-9) -3.997,-8.603 -4,-8.603 cw(c-4,-8) -4.603,-8 -4.603,-6 cw(c-4,-6) -4,-5.397 -2.802,-5.397 cw(c-2.802,-5.8) -2.398,-5.8 ccw(c-2.198,-5.8) -2.198,-6 v1(-2,-6)
S1_16.S4_N: P5.22 U16.J1 | length 13
  Top Layer w0.127: U16.J1@-2.5,-10.5 cw(c-2.5,-10.898) -2.102,-10.898 -2.102,-15.281 ccw(c-0.882,-15.281) -1.744,-16.143 ; -1.744,-16.144 cw(c-2.86,-17.26) -1.281,-17.26 -1.281,-21.681 cw(c-1.408,-21.681) -1.319,-21.771 -1.326,-21.779 cw(c-1.398,-21.707) -1.398,-21.809 ccw(c-1.398,-21.91) -1.47,-21.838 ccw(c-1.205,-22.104) -1.58,-22.104 P5.22@-1.58,-22.875
S1_16.S4_P: P5.24 U16.K1 | length 13
  Top Layer w0.127: U16.K1@-1.5,-10.5 ccw(c-1.5,-10.898) -1.898,-10.898 -1.898,-15.28 ccw(c-0.88,-15.28) -1.6,-16 -1.597,-16.003 cw(c-2.851,-17.256) -1.078,-17.256 -1.078,-21.681 ccw(c-0.951,-21.681) -1.041,-21.771 -1.034,-21.779 ccw(c-0.962,-21.707) -0.962,-21.809 cw(c-0.962,-21.91) -0.89,-21.838 cw(c-1.155,-22.104) -0.78,-22.104 P5.24@-0.78,-22.875
S1_16.S5_N: P5.28 U16.M5 | length 21.9
  Top Layer w0.127: U16.M5@0.5,-6.5 v1(1,-7) ; v2(0.712,-24.5) ccw(c0.533,-24.5) 0.66,-24.373 0.617,-24.33 cw(c0.847,-24.1) 0.522,-24.1 0.522,-24.08 cw(c0.674,-24.08) 0.566,-23.972 cw(c0.638,-24.044) 0.638,-23.942 ccw(c0.638,-23.84) 0.71,-23.912 0.751,-23.872 ccw(c0.582,-23.704) 0.82,-23.704 P5.28@0.82,-22.875
  Int2 (Sign) w0.076: v2(0.712,-24.5) ccw(c0.543,-24.5) 0.663,-24.38 cw(c1.003,-24.04) 0.522,-24.04 0.522,-15.111 ccw(c-1.11,-15.111) 0.044,-13.956 -0.038,-13.875 cw(c0.838,-13) -0.4,-13 -0.4,-7.702 cw(c0.7,-7.702) 0.7,-6.602 cw(c0.7,-6.902) 1,-6.902 v1(1,-7)
S1_16.S5_P: P5.26 U16.M6 | length 22.3
  Top Layer w0.127: P5.26@0.02,-22.875 0.02,-23.704 ccw(c0.259,-23.704) 0.09,-23.872 0.13,-23.912 ccw(c0.202,-23.84) 0.202,-23.942 cw(c0.202,-24.044) 0.274,-23.972 cw(c0.167,-24.08) 0.319,-24.08 0.319,-24.1 cw(c-0.006,-24.1) 0.223,-24.33 0.181,-24.373 ccw(c0.308,-24.5) v2(0.128,-24.5) ; U16.M6@0.5,-5.5 v1(1,-6)
  Int2 (Sign) w0.076: v2(0.128,-24.5) cw(c0.297,-24.5) 0.178,-24.38 ccw(c-0.163,-24.04) 0.319,-24.04 0.319,-15.111 ccw(c-1.111,-15.111) -0.1,-14.1 -0.182,-14.018 cw(c0.836,-13.001) -0.603,-13.001 -0.603,-7.702 cw(c0.7,-7.702) 0.7,-6.398 ccw(c0.7,-6.098) 1,-6.098 v1(1,-6)
S1_16.S6_N: P5.30 U16.L1 | length 13.4
  Top Layer w0.127: U16.L1@-0.5,-10.5 cw(c-0.5,-10.898) -0.102,-10.898 -0.102,-14.55 ccw(c2.64,-14.55) 0.701,-16.489 1.175,-16.962 cw(c-0.621,-18.758) 1.919,-18.758 1.919,-21.681 cw(c1.791,-21.681) 1.881,-21.771 1.874,-21.779 cw(c1.802,-21.707) 1.802,-21.809 ccw(c1.802,-21.91) 1.73,-21.838 ccw(c1.995,-22.104) 1.62,-22.104 P5.30@1.62,-22.875
S1_16.S6_P: P5.32 U16.M1 | length 13.4
  Top Layer w0.127: U16.M1@0.5,-10.5 ccw(c0.5,-10.898) 0.102,-10.898 0.102,-14.549 ccw(c2.642,-14.549) 0.846,-16.346 1.32,-16.82 cw(c-0.615,-18.755) 2.122,-18.755 2.122,-21.681 ccw(c2.249,-21.681) 2.159,-21.771 2.166,-21.779 ccw(c2.238,-21.707) 2.238,-21.809 cw(c2.238,-21.91) 2.31,-21.838 cw(c2.045,-22.104) 2.42,-22.104 P5.32@2.42,-22.875
S1_16.S7_N: P5.36 U16.R2 | length 20.7
  Top Layer w0.127: U16.R2@3.5,-9.5 v1(4,-10) ; v2(3.912,-24.5) ccw(c3.733,-24.5) 3.86,-24.373 3.817,-24.33 cw(c4.047,-24.1) 3.722,-24.1 3.722,-24.08 cw(c3.874,-24.08) 3.766,-23.972 cw(c3.838,-24.044) 3.838,-23.942 ccw(c3.838,-23.84) 3.91,-23.912 3.951,-23.872 ccw(c3.782,-23.704) 4.02,-23.704 P5.36@4.02,-22.875
  Int2 (Sign) w0.076: v2(3.912,-24.5) ccw(c3.743,-24.5) 3.863,-24.38 cw(c4.203,-24.04) 3.722,-24.04 3.722,-15.168 ccw(c0.985,-15.168) 2.92,-13.233 1.962,-12.275 cw(c2.838,-11.4) 1.6,-11.4 1.6,-10 cw(c1.998,-10) 1.998,-9.602 3.602,-9.602 cw(c3.602,-10) v1(4,-10)
S1_16.S7_P: P5.34 U16.R3 | length 21
  Top Layer w0.127: P5.34@3.22,-22.875 3.22,-23.704 ccw(c3.459,-23.704) 3.29,-23.872 3.33,-23.912 ccw(c3.402,-23.84) 3.402,-23.942 cw(c3.402,-24.044) 3.474,-23.972 cw(c3.367,-24.08) 3.519,-24.08 3.519,-24.1 cw(c3.193,-24.1) 3.423,-24.33 3.381,-24.373 ccw(c3.508,-24.5) v2(3.328,-24.5) ; U16.R3@3.5,-8.5 v1(4,-9)
  Int2 (Sign) w0.076: v2(3.328,-24.5) cw(c3.497,-24.5) 3.378,-24.38 ccw(c3.037,-24.04) 3.519,-24.04 3.519,-15.171 ccw(c0.979,-15.171) 2.775,-13.375 1.818,-12.418 cw(c2.834,-11.401) 1.397,-11.401 1.397,-10 cw(c1.998,-10) 1.998,-9.398 3.602,-9.398 ccw(c3.602,-9) v1(4,-9)
S1_16.S8_N: P5.38 U16.J4 | length 22.3
  Top Layer w0.127: v1(-3,-8) U16.J4@-2.5,-7.5 ; P5.38@4.82,-22.875 4.82,-23.704 ccw(c5.059,-23.704) 4.89,-23.872 4.93,-23.912 ccw(c5.002,-23.84) 5.002,-23.942 cw(c5.002,-24.044) 5.074,-23.972 cw(c4.966,-24.08) 5.118,-24.08 5.118,-24.1 cw(c4.793,-24.1) 5.023,-24.33 4.981,-24.373 ccw(c5.108,-24.5) v2(4.928,-24.5)
  Int7 (Sign) w0.076: v1(-3,-8) cw(c-3,-8.398) -2.602,-8.398 -2.602,-14.75 ccw(c0.14,-14.75) -1.799,-16.689 4.811,-23.299 cw(c4.07,-24.04) 5.118,-24.04 cw(c4.637,-24.04) 4.978,-24.38 ccw(c5.097,-24.5) v2(4.928,-24.5)
S1_16.S8_P: P5.40 U16.K4 | length 22.3
  Top Layer w0.127: v1(-2,-8) U16.K4@-1.5,-7.5 ; v2(5.512,-24.5) ccw(c5.333,-24.5) 5.46,-24.373 5.417,-24.33 cw(c5.647,-24.1) 5.322,-24.1 5.322,-24.08 cw(c5.474,-24.08) 5.366,-23.972 cw(c5.438,-24.044) 5.438,-23.942 ccw(c5.438,-23.84) 5.51,-23.912 5.55,-23.872 ccw(c5.382,-23.704) 5.62,-23.704 P5.40@5.62,-22.875
  Int7 (Sign) w0.076: v1(-2,-8) ccw(c-2,-8.398) -2.398,-8.398 -2.398,-14.749 ccw(c0.142,-14.749) -1.654,-16.546 4.957,-23.157 cw(c4.076,-24.038) 5.322,-24.038 5.322,-24.04 ccw(c5.803,-24.04) 5.463,-24.38 cw(c5.343,-24.5) v2(5.512,-24.5)
S1_16.S9_N: P5.44 U16.T4 | length 21.8
  Top Layer w0.127: U16.T4@4.5,-7.5 v1(5,-8) ; v2(11.112,-24.5) ccw(c10.932,-24.5) 11.059,-24.373 11.017,-24.33 cw(c11.247,-24.1) 10.922,-24.1 10.922,-24.08 cw(c11.074,-24.08) 10.966,-23.972 cw(c11.038,-24.044) 11.038,-23.942 ccw(c11.038,-23.84) 11.11,-23.912 11.15,-23.872 ccw(c10.981,-23.704) 11.22,-23.704 P5.44@11.22,-22.875
  Int7 (Sign) w0.076: v1(5,-8) ccw(c5,-8.398) 4.602,-8.398 4.602,-16.262 ccw(c7.142,-16.262) 5.346,-18.058 10.635,-23.348 cw(c9.944,-24.039) 10.922,-24.039 ccw(c11.403,-24.04) 11.063,-24.38 cw(c10.943,-24.5) v2(11.112,-24.5)
S1_16.S9_P: P5.42 U16.R4 | length 21.8
  Top Layer w0.127: U16.R4@3.5,-7.5 v1(4,-8) ; P5.42@10.42,-22.875 10.42,-23.704 ccw(c10.658,-23.704) 10.49,-23.872 10.53,-23.912 ccw(c10.602,-23.84) 10.602,-23.942 cw(c10.602,-24.044) 10.674,-23.972 cw(c10.566,-24.08) 10.718,-24.08 10.718,-24.1 cw(c10.393,-24.1) 10.623,-24.33 10.58,-24.373 ccw(c10.707,-24.5) v2(10.528,-24.5)
  Int7 (Sign) w0.076: v1(4,-8) cw(c4,-8.398) 4.398,-8.398 4.398,-16.263 ccw(c7.14,-16.263) 5.201,-18.201 10.491,-23.491 cw(c9.942,-24.04) 10.718,-24.04 cw(c10.237,-24.04) 10.577,-24.38 ccw(c10.697,-24.5) v2(10.528,-24.5)
S1_16.S10_N: P5.46 U16.P1 | length 20.2
  Top Layer w0.127: U16.P1@2.5,-10.5 cw(c2.5,-10.898) 2.898,-10.898 2.898,-16.357 ccw(c5.642,-16.357) 5.642,-19.1 10.5,-19.1 cw(c10.5,-20.918) 12.318,-20.918 12.318,-21.671 cw(c12.166,-21.671) 12.274,-21.779 cw(c12.202,-21.707) 12.202,-21.809 ccw(c12.202,-21.91) 12.13,-21.838 12.09,-21.878 ccw(c12.258,-22.047) 12.02,-22.047 P5.46@12.02,-22.875
S1_16.S10_P: P5.48 U16.R1 | length 20.2
  Top Layer w0.127: U16.R1@3.5,-10.5 ccw(c3.5,-10.898) 3.102,-10.898 3.102,-16.357 ccw(c5.642,-16.357) 5.642,-18.897 10.5,-18.897 cw(c10.5,-20.918) 12.521,-20.918 12.521,-21.671 ccw(c12.673,-21.671) 12.566,-21.779 ccw(c12.638,-21.707) 12.638,-21.809 cw(c12.638,-21.91) 12.71,-21.838 12.75,-21.878 cw(c12.581,-22.047) 12.82,-22.047 P5.48@12.82,-22.875
S1_16.S11_N: P5.52 U16.U1 | length 20
  Top Layer w0.127: U16.U1@5.5,-10.5 ccw(c5.5,-10.898) 5.102,-10.898 5.102,-14.857 ccw(c7.642,-14.857) 7.642,-17.397 12.6,-17.397 cw(c12.6,-18.918) 14.122,-18.918 14.122,-21.671 ccw(c14.274,-21.671) 14.166,-21.779 ccw(c14.238,-21.707) 14.238,-21.809 cw(c14.238,-21.91) 14.31,-21.838 14.35,-21.878 cw(c14.181,-22.047) 14.42,-22.047 P5.52@14.42,-22.875
S1_16.S11_P: P5.50 U16.T1 | length 20
  Top Layer w0.127: U16.T1@4.5,-10.5 cw(c4.5,-10.898) 4.898,-10.898 4.898,-14.857 ccw(c7.642,-14.857) 7.642,-17.6 12.6,-17.6 cw(c12.6,-18.918) 13.918,-18.918 13.918,-21.671 cw(c13.766,-21.671) 13.874,-21.779 cw(c13.802,-21.707) 13.802,-21.809 ccw(c13.802,-21.91) 13.73,-21.838 13.69,-21.878 ccw(c13.858,-22.047) 13.62,-22.047 P5.50@13.62,-22.875
S1_16.S12_N: P5.54 U16.N5 | length 30.8
  Top Layer w0.127: U16.N5@1.5,-6.5 v1(2,-7) ; P5.54@15.22,-22.875 15.22,-23.704 ccw(c15.458,-23.704) 15.289,-23.872 15.33,-23.912 ccw(c15.402,-23.84) 15.402,-23.942 cw(c15.402,-24.044) 15.474,-23.972 cw(c15.366,-24.08) 15.518,-24.08 15.518,-24.1 cw(c15.193,-24.1) 15.423,-24.33 15.38,-24.373 ccw(c15.507,-24.5) v2(15.328,-24.5)
  Int2 (Sign) w0.076: v1(2,-7) 2,-6.5 cw(c2.1,-6.5) 2.1,-6.4 cw(c2.1,-6.641) 2.271,-6.471 2.3,-6.5 ccw(c2.541,-6.259) 2.541,-6.6 cw(c2.541,-6.676) 2.543,-6.6 2.691,-6.603 ccw(c2.7,-6.159) 2.7,-6.603 ; 2.616,-6.603 2.7,-6.603 ; v2(15.328,-24.5) cw(c15.497,-24.5) 15.377,-24.38 ccw(c15.037,-24.04) 15.518,-24.04 ccw(c14.741,-24.04) 15.29,-23.49 14.144,-22.344 ccw(c12.348,-24.14) 12.348,-21.6 9.1,-21.6 cw(c9.1,-18.9) 6.4,-18.9 6.4,-13.261 ccw(c5.258,-13.261) 6.065,-12.453 5.955,-12.343 cw(c7.296,-11.002) 5.4,-11.002 5.4,-8.003 ccw(c5,-8.003) 5,-7.603 cw(c5,-7.003) 4.4,-7.003 ccw(c4,-7.003) 4,-6.603 2.7,-6.603
S1_16.S12_P: P5.56 U16.P6 | length 30.9
  Top Layer w0.127: U16.P6@2.5,-5.5 v1(3,-6) ; v2(15.912,-24.5) ccw(c15.732,-24.5) 15.859,-24.373 15.817,-24.33 cw(c16.046,-24.1) 15.721,-24.1 15.721,-24.08 cw(c15.873,-24.08) 15.766,-23.972 cw(c15.838,-24.044) 15.838,-23.942 ccw(c15.838,-23.84) 15.91,-23.912 15.95,-23.872 ccw(c15.781,-23.704) 16.02,-23.704 P5.56@16.02,-22.875
  Int2 (Sign) w0.076: v1(3,-6) 2.5,-6 ccw(c2.5,-6.1) 2.4,-6.1 ccw(c2.641,-6.1) 2.471,-6.271 2.529,-6.329 ccw(c2.7,-6.159) 2.7,-6.4 4,-6.4 cw(c4,-7.003) 4.603,-7.003 ccw(c5,-7.003) 5,-7.4 cw(c5,-8.003) 5.603,-8.003 5.603,-11 ccw(c7.301,-11) 6.1,-12.2 6.21,-12.31 cw(c5.26,-13.26) 6.603,-13.26 6.603,-18.9 ccw(c9.1,-18.9) 9.1,-21.397 12.351,-21.397 cw(c12.351,-24.132) 14.285,-22.198 15.436,-23.348 cw(c14.746,-24.038) 15.721,-24.038 15.721,-24.04 ccw(c16.203,-24.04) 15.862,-24.38 cw(c15.743,-24.5) v2(15.912,-24.5)
S1_16.S13_N: P5.60 U16.V2 | length 22.9
  Top Layer w0.127: U16.V2@6.5,-9.5 ccw(c6.5,-9.898) 6.102,-9.898 6.102,-13.25 ccw(c8.252,-13.25) 8.252,-15.4 14.578,-15.4 cw(c14.578,-18.143) 17.321,-18.143 17.321,-21.671 ccw(c17.474,-21.671) 17.366,-21.779 ccw(c17.438,-21.707) 17.438,-21.809 cw(c17.438,-21.91) 17.51,-21.838 17.55,-21.878 cw(c17.381,-22.047) 17.62,-22.047 P5.60@17.62,-22.875
S1_16.S13_P: P5.58 U16.U2 | length 22.9
  Top Layer w0.127: U16.U2@5.5,-9.5 cw(c5.5,-9.898) 5.898,-9.898 5.898,-13.25 ccw(c8.252,-13.25) 8.252,-15.603 14.578,-15.603 cw(c14.578,-18.143) 17.118,-18.143 17.118,-21.671 cw(c16.966,-21.671) 17.074,-21.779 cw(c17.002,-21.707) 17.002,-21.809 ccw(c17.002,-21.91) 16.93,-21.838 16.89,-21.878 ccw(c17.058,-22.047) 16.82,-22.047 P5.58@16.82,-22.875
S1_16.S14_N: P5.62 U16.H15 | length 47.7
  Top Layer w0.127: v1(-4,4) U16.H15@-3.5,3.5 ; P5.62@18.42,-22.875 18.42,-23.704 ccw(c18.658,-23.704) 18.489,-23.872 18.529,-23.912 ccw(c18.601,-23.84) 18.601,-23.942 cw(c18.601,-24.044) 18.673,-23.972 cw(c18.566,-24.08) 18.718,-24.08 18.718,-24.1 cw(c18.393,-24.1) 18.623,-24.33 18.58,-24.373 ccw(c18.707,-24.5) v2(18.528,-24.5)
  Int2 (Sign) w0.076: v1(-4,4) cw(c-4,3.603) -3.603,3.603 -3.603,-1 ccw(c-3.003,-1) -3.003,-1.6 6,-1.6 cw(c6,-1.997) 6.397,-1.997 6.397,-4 ccw(c7,-4) 7,-4.603 8,-4.603 cw(c8,-5.003) 8.4,-5.003 8.4,-9.003 ccw(c9,-9.003) 9,-9.603 11,-9.603 cw(c11,-10) 11.397,-10 11.397,-10.002 ccw(c14.04,-10.002) 12.171,-11.871 13.972,-13.672 cw(c12.947,-14.697) 14.397,-14.697 14.397,-17.249 ccw(c15.237,-17.249) 14.642,-17.842 ccw(c15.237,-17.249) 14.643,-17.843 17.974,-21.174 cw(c16.178,-22.97) 18.718,-22.97 18.718,-24.04 cw(c18.237,-24.04) 18.577,-24.38 ccw(c18.697,-24.5) v2(18.528,-24.5)
S1_16.S14_P: P5.64 U16.J15 | length 47.7
  Top Layer w0.127: v1(-3,4) U16.J15@-2.5,3.5 ; v2(19.112,-24.5) ccw(c18.932,-24.5) 19.059,-24.373 19.017,-24.33 cw(c19.246,-24.1) 18.921,-24.1 18.921,-24.08 cw(c19.073,-24.08) 18.966,-23.972 cw(c19.038,-24.044) 19.038,-23.942 ccw(c19.038,-23.84) 19.11,-23.912 19.15,-23.872 ccw(c18.981,-23.704) 19.22,-23.704 P5.64@19.22,-22.875
  Int2 (Sign) w0.076: v1(-3,4) ccw(c-3,3.6) -3.4,3.6 -3.4,-1 ccw(c-3.003,-1) -3.003,-1.397 6,-1.397 cw(c6,-1.997) 6.6,-1.997 6.6,-4 ccw(c7,-4) 7,-4.4 8,-4.4 cw(c8,-5.003) 8.603,-5.003 8.603,-9.003 ccw(c9,-9.003) 9,-9.4 11,-9.4 cw(c11,-10) 11.6,-10 ccw(c14.045,-10) 12.316,-11.729 14.116,-13.529 cw(c12.949,-14.697) 14.6,-14.697 14.6,-17.247 ccw(c15.241,-17.247) 14.788,-17.7 18.12,-21.032 cw(c16.184,-22.968) 18.921,-22.968 18.921,-24.04 ccw(c19.403,-24.04) 19.062,-24.38 cw(c18.943,-24.5) v2(19.112,-24.5)
S1_16.S15_N: P5.68 U16.Y1 | length 23.1
  Top Layer w0.127: U16.Y1@8.5,-10.5 ccw(c8.5,-10.898) 8.102,-10.898 8.102,-11.002 ccw(c9.55,-11.002) 8.526,-12.026 8.656,-12.156 ccw(c10.452,-10.36) 10.452,-12.9 17.778,-12.9 cw(c17.778,-15.643) 20.521,-15.643 20.521,-21.671 ccw(c20.674,-21.671) 20.566,-21.779 ccw(c20.638,-21.707) 20.638,-21.809 cw(c20.638,-21.91) 20.71,-21.838 20.75,-21.878 cw(c20.581,-22.047) 20.82,-22.047 P5.68@20.82,-22.875
S1_16.S15_P: P5.66 U16.W1 | length 23.1
  Top Layer w0.127: U16.W1@7.5,-10.5 cw(c7.5,-10.898) 7.898,-10.898 7.898,-11.003 ccw(c9.546,-11.003) 8.381,-12.168 8.556,-12.344 ccw(c10.39,-10.51) 10.39,-13.103 17.778,-13.103 cw(c17.778,-15.643) 20.318,-15.643 20.318,-21.671 cw(c20.166,-21.671) 20.274,-21.779 cw(c20.202,-21.707) 20.202,-21.809 ccw(c20.202,-21.91) 20.13,-21.838 20.09,-21.878 ccw(c20.258,-22.047) 20.02,-22.047 P5.66@20.02,-22.875
S1_16.S16_N: P5.70 U16.W4 | length 31.2
  Top Layer w0.127: U16.W4@7.5,-7.5 v1(8,-8) ; P5.70@21.62,-22.875 21.62,-23.704 ccw(c21.858,-23.704) 21.689,-23.872 21.729,-23.912 ccw(c21.801,-23.84) 21.801,-23.942 cw(c21.801,-24.044) 21.873,-23.972 cw(c21.766,-24.08) 21.918,-24.08 21.918,-24.1 cw(c21.593,-24.1) 21.823,-24.33 21.78,-24.373 ccw(c21.907,-24.5) v2(21.728,-24.5)
  Int7 (Sign) w0.076: v1(8,-8) 7.802,-8 cw(c7.802,-7.8) 7.602,-7.8 ccw(c7.198,-7.8) 7.198,-7.397 7,-7.397 ccw(c7,-8) 6.397,-8 ccw(c6.997,-8) 6.997,-8.6 7,-8.6 cw(c7,-9) 7.4,-9 7.4,-14.184 ccw(c8.819,-14.184) 8.819,-15.603 13.251,-15.603 cw(c13.251,-18.143) 15.047,-16.347 21.337,-22.637 cw(c19.933,-24.04) 21.918,-24.04 cw(c21.437,-24.04) 21.777,-24.38 ccw(c21.897,-24.5) v2(21.728,-24.5)
S1_16.S16_P: P5.72 U16.V4 | length 30.5
  Top Layer w0.127: U16.V4@6.5,-7.5 v1(7,-8) ; v2(22.312,-24.5) ccw(c22.132,-24.5) 22.259,-24.373 22.216,-24.33 cw(c22.446,-24.1) 22.121,-24.1 22.121,-24.08 cw(c22.273,-24.08) 22.166,-23.972 cw(c22.238,-24.044) 22.238,-23.942 ccw(c22.238,-23.84) 22.31,-23.912 22.35,-23.872 ccw(c22.181,-23.704) 22.42,-23.704 P5.72@22.42,-22.875
  Int7 (Sign) w0.076: v1(7,-8) 7.198,-8 ccw(c7.198,-7.8) 7.398,-7.8 ccw(c7.198,-7.8) 7.198,-7.6 7,-7.6 ccw(c7,-8) 6.6,-8 ccw(c6.997,-8) 6.997,-8.397 7,-8.397 cw(c7,-9) 7.603,-9 7.603,-14.1 ccw(c8.903,-14.1) 8.903,-15.4 13.252,-15.4 cw(c13.252,-18.141) 15.19,-16.203 21.481,-22.493 cw(c19.935,-24.039) 22.121,-24.039 ccw(c22.603,-24.04) 22.262,-24.38 cw(c22.143,-24.5) v2(22.312,-24.5)
S17_32.S17_N: P5.11 U16.G3 | length 23.6
  Top Layer w0.127: v2(-5.688,-27) cw(c-5.867,-27) -5.74,-27.127 -5.783,-27.17 ccw(c-5.553,-27.4) -5.878,-27.4 ccw(c-5.726,-27.4) -5.833,-27.508 ccw(c-5.761,-27.436) -5.761,-27.538 cw(c-5.761,-27.64) -5.689,-27.568 -5.649,-27.608 cw(c-5.818,-27.776) -5.58,-27.776 P5.11@-5.58,-28.605 ; v1(-5,-9) U16.G3@-4.5,-8.5
  Int7 (Sign) w0.076: v2(-5.688,-27) ccw(c-5.857,-27) -5.737,-26.88 cw(c-5.397,-26.54) -5.878,-26.54 cw(c-5.034,-26.54) -5.631,-25.943 -5.103,-25.415 ccw(c-7.041,-23.477) -4.3,-23.477 -4.3,-18.284 ; v1(-5,-9) -4.755,-9 ccw(c-4.755,-8.847) -4.602,-8.847 cw(c-4.151,-8.847) -4.151,-8.397 -4,-8.397 cw(c-4,-8.998) -3.398,-8.998 -3.398,-13.3 cw(c-5.296,-13.3) -3.954,-14.641 -3.956,-14.644 ccw(c-3.127,-15.473) -4.3,-15.473 -4.3,-18.248
S17_32.S17_P: P5.9 U16.H3 | length 23
  Top Layer w0.127: P5.9@-6.38,-28.605 -6.38,-27.776 cw(c-6.141,-27.776) -6.31,-27.608 -6.27,-27.568 cw(c-6.198,-27.64) -6.198,-27.538 ccw(c-6.198,-27.436) -6.126,-27.508 ccw(c-6.233,-27.4) -6.081,-27.4 ccw(c-6.406,-27.4) -6.176,-27.17 -6.219,-27.127 cw(c-6.092,-27) v2(-6.272,-27) ; v1(-4,-9) U16.H3@-3.5,-8.5
  Int7 (Sign) w0.076: v2(-6.272,-27) cw(c-6.103,-27) -6.222,-26.88 ccw(c-6.563,-26.54) -6.081,-26.54 -6.081,-26.537 cw(c-5.042,-26.537) -5.777,-25.802 -5.247,-25.272 ccw(c-7.043,-23.476) -4.503,-23.476 -4.503,-15.471 cw(c-3.133,-15.471) -4.102,-14.502 -4.1,-14.5 ccw(c-5.303,-13.297) -3.602,-13.297 -3.602,-8.998 ccw(c-4,-8.998) -4,-8.6 -4.151,-8.6 ccw(c-4.151,-8.847) -4.398,-8.847 ccw(c-4.246,-8.847) -4.246,-9 v1(-4,-9)
S17_32.S18_N: P5.13 U16.E3 | length 21.4
  Top Layer w0.127: v1(-7,-9) U16.E3@-6.5,-8.5 ; P5.13@-4.78,-28.605 -4.78,-27.776 cw(c-4.541,-27.776) -4.71,-27.608 -4.67,-27.568 cw(c-4.598,-27.64) -4.598,-27.538 ccw(c-4.598,-27.436) -4.526,-27.508 ccw(c-4.634,-27.4) -4.481,-27.4 ccw(c-4.807,-27.4) -4.577,-27.17 -4.619,-27.127 cw(c-4.492,-27) v2(-4.672,-27)
  Int2 (Sign) w0.076: v1(-7,-9) cw(c-7,-9.398) -6.602,-9.398 -6.602,-21.464 ccw(c-3.86,-21.464) -5.799,-23.403 -5.287,-23.914 cw(c-5.974,-24.6) -5.003,-24.6 -5.003,-25.128 ccw(c-3.631,-25.128) -4.601,-26.099 -4.6,-26.1 cw(c-4.886,-26.386) -4.481,-26.386 -4.481,-26.54 cw(c-4.963,-26.54) -4.622,-26.88 ccw(c-4.503,-27) v2(-4.672,-27)
S17_32.S18_P: P5.15 U16.F3 | length 21.4
  Top Layer w0.127: v1(-6,-9) U16.F3@-5.5,-8.5 ; v2(-4.088,-27) cw(c-4.267,-27) -4.14,-27.127 -4.183,-27.17 ccw(c-3.953,-27.4) -4.278,-27.4 ccw(c-4.126,-27.4) -4.234,-27.508 ccw(c-4.162,-27.436) -4.162,-27.538 cw(c-4.162,-27.64) -4.09,-27.568 -4.05,-27.608 cw(c-4.218,-27.776) -3.98,-27.776 P5.15@-3.98,-28.605
  Int2 (Sign) w0.076: v1(-6,-9) ccw(c-6,-9.398) -6.398,-9.398 -6.398,-21.463 ccw(c-3.858,-21.463) -5.654,-23.259 -5.142,-23.772 cw(c-5.968,-24.598) -4.8,-24.598 -4.8,-25.127 ccw(c-3.627,-25.127) -4.456,-25.956 ; -4.456,-25.957 cw(c-4.884,-26.385) -4.278,-26.385 -4.278,-26.54 ccw(c-3.797,-26.54) -4.137,-26.88 cw(c-4.257,-27) v2(-4.088,-27)
S17_32.S19_N: P5.19 U16.G2 | length 22.2
  Top Layer w0.127: v1(-5,-10) U16.G2@-4.5,-9.5 ; v2(-2.488,-27) cw(c-2.667,-27) -2.54,-27.127 -2.583,-27.17 ccw(c-2.353,-27.4) -2.678,-27.4 ccw(c-2.526,-27.4) -2.633,-27.508 ccw(c-2.561,-27.436) -2.561,-27.538 cw(c-2.561,-27.64) -2.489,-27.568 -2.449,-27.608 cw(c-2.618,-27.776) -2.38,-27.776 P5.19@-2.38,-28.605
  Int2 (Sign) w0.076: v1(-5,-10) -4.802,-10 ccw(c-4.802,-9.8) -4.602,-9.8 ccw(c-4.802,-9.8) -4.802,-9.6 -5,-9.6 ccw(c-5,-10) -5.4,-10 -5.4,-21.676 ccw(c-4.376,-21.676) -5.1,-22.4 -4.153,-23.347 cw(c-5.005,-24.199) -3.8,-24.199 -3.8,-24.839 ccw(c-3.139,-24.839) -3.606,-25.306 -2.856,-26.056 cw(c-3.286,-26.486) -2.678,-26.486 -2.678,-26.54 ccw(c-2.197,-26.54) -2.537,-26.88 cw(c-2.657,-27) v2(-2.488,-27)
S17_32.S19_P: P5.17 U16.H2 | length 22.8
  Top Layer w0.127: v1(-4,-10) U16.H2@-3.5,-9.5 ; P5.17@-3.18,-28.605 -3.18,-27.776 cw(c-2.941,-27.776) -3.11,-27.608 -3.07,-27.568 cw(c-2.998,-27.64) -2.998,-27.538 ccw(c-2.998,-27.436) -2.926,-27.508 ccw(c-3.033,-27.4) -2.881,-27.4 ccw(c-3.206,-27.4) -2.976,-27.17 -3.019,-27.127 cw(c-2.892,-27) v2(-3.072,-27)
  Int2 (Sign) w0.076: v1(-4,-10) -4.198,-10 cw(c-4.198,-9.8) -4.398,-9.8 ccw(c-4.802,-9.8) -4.802,-9.397 -5,-9.397 ccw(c-5,-10) -5.603,-10 -5.603,-21.677 ccw(c-4.378,-21.677) -5.244,-22.543 -4.297,-23.49 cw(c-5.007,-24.2) -4.003,-24.2 -4.003,-24.84 ccw(c-3.142,-24.84) -3.751,-25.449 -3.75,-25.45 -3,-26.2 cw(c-3.287,-26.487) -2.881,-26.487 -2.881,-26.54 cw(c-3.363,-26.54) -3.022,-26.88 ccw(c-2.903,-27) v2(-3.072,-27)
S17_32.S20_N: P5.21 U16.H5 | length 23.9
  Top Layer w0.127: v1(-4,-7) U16.H5@-3.5,-6.5 ; P5.21@-1.58,-28.605 -1.58,-27.776 cw(c-1.341,-27.776) -1.51,-27.608 -1.47,-27.568 cw(c-1.398,-27.64) -1.398,-27.538 ccw(c-1.398,-27.436) -1.326,-27.508 ccw(c-1.434,-27.4) -1.281,-27.4 ccw(c-1.607,-27.4) -1.377,-27.17 -1.419,-27.127 cw(c-1.292,-27) v2(-1.472,-27)
  Int2 (Sign) w0.076: v1(-4,-7) -3.802,-7 cw(c-3.802,-7.2) -3.602,-7.2 ccw(c-3.198,-7.2) -3.198,-7.603 -2.997,-7.603 cw(c-2.997,-8) -2.6,-8 -2.6,-13.302 ccw(c-0.704,-13.302) -2.045,-14.643 -2.044,-14.644 cw(c-3.115,-15.715) -1.6,-15.715 -1.6,-25.318 ccw(c-0.919,-25.318) -1.401,-25.799 ; v2(-1.472,-27) cw(c-1.303,-27) -1.422,-26.88 ccw(c-1.763,-26.54) -1.281,-26.54 -1.281,-26.086 ccw(c-1.686,-26.086) -1.4,-25.8
S17_32.S20_P: P5.23 U16.J5 | length 23.9
  Top Layer w0.127: v1(-3,-7) U16.J5@-2.5,-6.5 ; v2(-0.888,-27) cw(c-1.067,-27) -0.94,-27.127 -0.983,-27.17 ccw(c-0.753,-27.4) -1.078,-27.4 ccw(c-0.926,-27.4) -1.034,-27.508 ccw(c-0.962,-27.436) -0.962,-27.538 cw(c-0.962,-27.64) -0.89,-27.568 -0.85,-27.608 cw(c-1.018,-27.776) -0.78,-27.776 P5.23@-0.78,-28.605
  Int2 (Sign) w0.076: v1(-3,-7) -3.198,-7 ccw(c-3.198,-7.2) -3.398,-7.2 ccw(c-3.198,-7.2) -3.198,-7.4 -2.997,-7.4 cw(c-2.997,-8) -2.397,-8 -2.397,-13.301 ccw(c-0.701,-13.301) -1.9,-14.5 -1.899,-14.501 cw(c-3.111,-15.713) -1.397,-15.713 -1.397,-25.317 ccw(c-0.917,-25.317) -1.256,-25.656 ; -1.256,-25.657 cw(c-1.684,-26.085) -1.078,-26.085 -1.078,-26.54 ccw(c-0.597,-26.54) -0.937,-26.88 cw(c-1.057,-27) v2(-0.888,-27)
S17_32.S21_N: P5.27 U16.L4 | length 23.2
  Top Layer w0.127: v1(-1,-8) U16.L4@-0.5,-7.5 ; v2(0.712,-27) cw(c0.533,-27) 0.66,-27.127 0.617,-27.17 ccw(c0.847,-27.4) 0.522,-27.4 ccw(c0.674,-27.4) 0.566,-27.508 ccw(c0.638,-27.436) 0.638,-27.538 cw(c0.638,-27.64) 0.71,-27.568 0.751,-27.608 cw(c0.582,-27.776) 0.82,-27.776 P5.27@0.82,-28.605
  Int2 (Sign) w0.076: v1(-1,-8) -1,-7.746 ccw(c-1.145,-7.746) -1.145,-7.602 ccw(c-1.145,-7.857) -1.4,-7.857 -1.4,-13.034 ccw(c-0.034,-13.034) -1,-14 cw(c-2.454,-15.455) -0.397,-15.455 -0.397,-24.793 ccw(c1.108,-24.793) 0.044,-25.857 0.335,-26.148 cw(c-0.115,-26.598) 0.522,-26.598 ; 0.522,-26.598 0.522,-26.6 ccw(c0.859,-26.6) 0.62,-26.838 0.663,-26.88 cw(c0.543,-27) v2(0.712,-27)
S17_32.S21_P: P5.25 U16.L5 | length 23.5
  Top Layer w0.127: v1(-1,-7) U16.L5@-0.5,-6.5 ; P5.25@0.02,-28.605 0.02,-27.776 cw(c0.259,-27.776) 0.09,-27.608 0.13,-27.568 cw(c0.202,-27.64) 0.202,-27.538 ccw(c0.202,-27.436) 0.274,-27.508 ccw(c0.167,-27.4) 0.319,-27.4 ccw(c-0.006,-27.4) 0.224,-27.17 0.181,-27.127 cw(c0.308,-27) v2(0.128,-27)
  Int2 (Sign) w0.076: v1(-1,-7) -1,-7.254 cw(c-1.145,-7.254) -1.145,-7.398 ccw(c-1.145,-7.857) -1.603,-7.857 -1.603,-13.036 ccw(c-0.039,-13.036) -1.145,-14.142 -1.144,-14.144 cw(c-2.456,-15.456) -0.6,-15.456 -0.6,-24.794 ccw(c1.103,-24.794) -0.101,-25.999 0.191,-26.291 ; v2(0.128,-27) cw(c0.297,-27) 0.178,-26.88 v2@0.22,-26.838 ; 0.191,-26.291 cw(c-0.119,-26.6) 0.319,-26.6 cw(c-0.018,-26.6) v2@0.22,-26.838
S17_32.S22_N: P5.29 U16.N3 | length 26.8
  Top Layer w0.127: U16.N3@1.5,-8.5 v1(2,-9) ; P5.29@1.62,-28.605 1.62,-27.776 cw(c1.859,-27.776) 1.69,-27.608 1.73,-27.568 cw(c1.802,-27.64) 1.802,-27.538 ccw(c1.802,-27.436) 1.874,-27.508 ccw(c1.766,-27.4) 1.918,-27.4 ccw(c1.593,-27.4) 1.823,-27.17 1.781,-27.127 cw(c1.908,-27) v2(1.728,-27)
  Int2 (Sign) w0.076: v2(1.728,-27) cw(c1.897,-27) 1.778,-26.88 ccw(c1.437,-26.54) 1.918,-26.54 1.918,-26.227 ccw(c1.173,-26.227) 1.7,-25.7 1.699,-25.699 cw(c2.42,-24.978) 1.4,-24.978 1.4,-15.298 ccw(c-0.798,-15.298) 0.756,-13.744 0.7,-13.687 cw(c2.639,-11.749) -0.103,-11.749 -0.103,-8.1 cw(c0.6,-8.1) 0.6,-7.397 2,-7.397 cw(c2,-8) 2.603,-8 2.603,-8.198 cw(c2.2,-8.198) 2.2,-8.602 ccw(c2.2,-8.802) 2,-8.802 v1(2,-9)
S17_32.S22_P: P5.31 U16.N4 | length 25.9
  Top Layer w0.127: U16.N4@1.5,-7.5 v1(2,-8) ; v2(2.312,-27) cw(c2.133,-27) 2.26,-27.127 2.217,-27.17 ccw(c2.447,-27.4) 2.122,-27.4 ccw(c2.274,-27.4) 2.166,-27.508 ccw(c2.238,-27.436) 2.238,-27.538 cw(c2.238,-27.64) 2.31,-27.568 2.35,-27.608 cw(c2.182,-27.776) 2.42,-27.776 P5.31@2.42,-28.605
  Int2 (Sign) w0.076: 1.844,-25.557 cw(c1.175,-26.226) 2.122,-26.226 2.122,-26.54 ccw(c2.603,-26.54) 2.263,-26.88 cw(c2.143,-27) v2(2.312,-27) ; 1.844,-25.556 cw(c2.424,-24.976) 1.603,-24.976 1.603,-15.297 ccw(c-0.796,-15.297) 0.901,-13.601 0.844,-13.544 cw(c2.64,-11.748) 0.1,-11.748 0.1,-8.1 cw(c0.6,-8.1) 0.6,-7.6 2,-7.6 cw(c2,-8) 2.4,-8 2.4,-8.198 cw(c2.2,-8.198) 2.2,-8.398 cw(c2.2,-8.198) 2,-8.198 v1(2,-8)
S17_32.S23_N: P5.35 U16.M2 | length 21.5
  Top Layer w0.127: U16.M2@0.5,-9.5 v1(1,-10) ; v2(3.912,-27) cw(c3.733,-27) 3.86,-27.127 3.817,-27.17 ccw(c4.047,-27.4) 3.722,-27.4 ccw(c3.874,-27.4) 3.766,-27.508 ccw(c3.838,-27.436) 3.838,-27.538 cw(c3.838,-27.64) 3.91,-27.568 3.951,-27.608 cw(c3.782,-27.776) 4.02,-27.776 P5.35@4.02,-28.605
  Int2 (Sign) w0.076: v1(1,-10) 1,-9.802 ccw(c0.8,-9.802) 0.8,-9.602 ccw(c0.8,-9.802) 0.6,-9.802 0.6,-11.048 ccw(c3.14,-11.048) 1.344,-12.844 1.817,-13.317 cw(c-0.074,-15.208) 2.6,-15.208 2.6,-24.2 ccw(c4.079,-24.2) 3.033,-25.246 3.324,-25.537 cw(c2.364,-26.497) 3.722,-26.497 3.722,-26.54 ccw(c4.203,-26.54) 3.863,-26.88 cw(c3.743,-27) v2(3.912,-27)
S17_32.S23_P: P5.33 U16.M3 | length 21.9
  Top Layer w0.127: U16.M3@0.5,-8.5 v1(1,-9) ; P5.33@3.22,-28.605 3.22,-27.776 cw(c3.459,-27.776) 3.29,-27.608 3.33,-27.568 cw(c3.402,-27.64) 3.402,-27.538 ccw(c3.402,-27.436) 3.474,-27.508 ccw(c3.367,-27.4) 3.519,-27.4 ccw(c3.193,-27.4) 3.424,-27.17 3.381,-27.127 cw(c3.508,-27) v2(3.328,-27)
  Int2 (Sign) w0.076: v1(1,-9) 1,-9.198 cw(c0.8,-9.198) 0.8,-9.398 ccw(c0.8,-9.802) 0.397,-9.802 0.397,-11.048 ccw(c3.139,-11.048) 1.2,-12.987 1.671,-13.459 cw(c-0.08,-15.21) 2.397,-15.21 2.397,-24.201 ccw(c4.078,-24.201) 2.889,-25.389 3.178,-25.678 cw(c2.357,-26.5) 3.519,-26.5 3.519,-26.54 cw(c3.037,-26.54) 3.378,-26.88 ccw(c3.497,-27) v2(3.328,-27)
S17_32.S24_N: P5.37 U16.K3 | length 24.3
  Top Layer w0.127: v1(-2,-9) U16.K3@-1.5,-8.5 ; P5.37@4.82,-28.605 4.82,-27.776 cw(c5.059,-27.776) 4.89,-27.608 4.93,-27.568 cw(c5.002,-27.64) 5.002,-27.538 ccw(c5.002,-27.436) 5.074,-27.508 ccw(c4.966,-27.4) 5.118,-27.4 ccw(c4.793,-27.4) 5.023,-27.17 4.981,-27.127 cw(c5.108,-27) v2(4.928,-27)
  Int7 (Sign) w0.076: v1(-2,-9) cw(c-2,-9.398) -1.602,-9.398 -1.602,-14.15 ccw(c1.14,-14.15) -0.799,-16.088 6.007,-22.894 cw(c5.057,-23.844) 6.4,-23.844 cw(c4.544,-23.844) 5.856,-25.156 5.575,-25.438 ccw(c6.676,-26.539) 5.118,-26.539 ; v2(4.928,-27) cw(c5.097,-27) 4.978,-26.88 ccw(c4.637,-26.54) 5.118,-26.54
